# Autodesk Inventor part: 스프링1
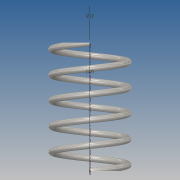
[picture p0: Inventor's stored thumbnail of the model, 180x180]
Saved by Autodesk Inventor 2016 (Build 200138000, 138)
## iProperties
Created: 2016-01
Part Number: 스프링1
Material: 스테인레스 스틸
Document SubType Name: Modeling
Designer: Administrator
Density: 8 g/cm^3
Appearance: 반연마
Mass: 8.55991 g
Surface Area: 21.737 cm^2
Volume: 1.06999 cm^3
Author: Administrator
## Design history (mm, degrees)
sketch "스케치1"
  geometry: L1 (0, 0)-(11, 0); L2 (11, 0)-(11, 39.695); L3 (11, 39.695)-(0, 39.695); L4 (0, 39.695)-(0, 0); C1 r 1 at (11, 0)
  constraints: 8 end point, 2 parallel, 1 centre point, 1 coincident, 1 horizontal, 1 perpendicular
  dimensions: "d0" = 2 diameter of C1; "d1" = 39.69541 distance of L1.end L2.end (derived); "d2" = 22 diameter of L2 L4
feature "코일1" pitch "d3" = 10; turns "d5" = 5; dims "d4" = 39.69541 (= d1), "d6" = 0, angle "d7" = 90 deg, angle "d8" = 90 deg, "d9" = 0, "d10" = 0
sketch "스케치2"
  geometry: L1 (5.3, 0)-(-21.597, 0); L2 (-21.597, 0)-(-21.597, -10.619); L3 (-21.597, -10.619)-(5.3, -10.619); L4 (5.3, -10.619)-(5.3, 0); 3 further points
  constraints: 8 end point, 2 parallel, 1 horizontal, 1 horizontal alignment, 1 perpendicular, 1 point on line
extrude "돌출1" cut sketch "스케치2" stored distance "d11" = 0; taper "d12" = 0 deg
sketch "스케치3"
  geometry: L1 (-4.261, 0)-(22.454, 0); L2 (22.454, 0)-(22.454, 6.999); L3 (22.454, 6.999)-(-4.261, 6.999); L4 (-4.261, 6.999)-(-4.261, 0); 3 further points
  constraints: 8 end point, 2 parallel, 1 horizontal, 1 horizontal alignment, 1 perpendicular, 1 point on line
extrude "돌출2" cut sketch "스케치3" stored distance "d13" = 0; taper "d14" = 0 deg
node "솔리드1"
